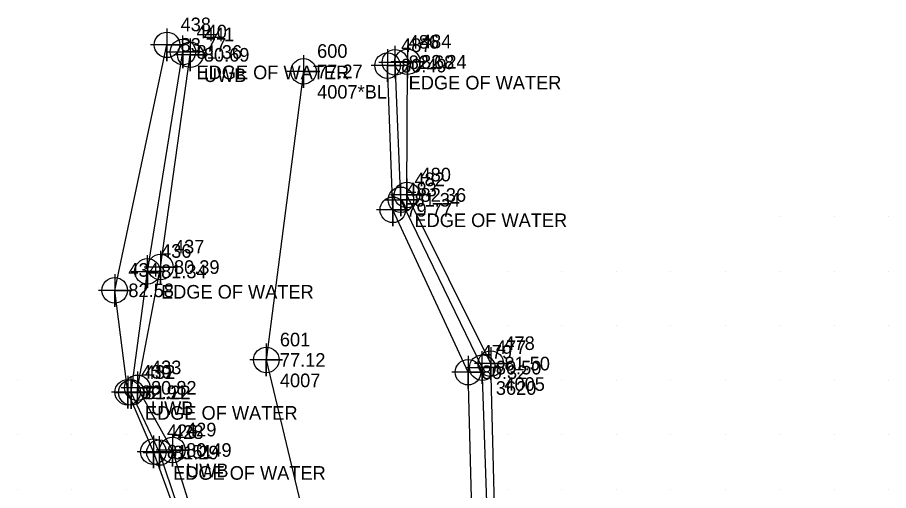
# Model space of a CAD drawing. Extents: x 1988140 to 1988766, y 249950 to 250250.
# Drawn here: x 1988380 to 1988540, y 250109.7 to 250196.6 of the extents above; entities that cross this region are included whole.
import ezdxf

# ---------------------------------------------------------------- set-up
doc = ezdxf.new("R2010")
doc.units = 0
for name, color, linetype in [('Exist DTM Breakline', 7, 'Continuous'), ('Exist DTM Breakline Cogo Comment', 7, 'Continuous'), ('Exist DTM Breakline Cogo Elevation', 7, 'Continuous'), ('Exist DTM Breakline Cogo Number', 7, 'Continuous'), ('Exist DTM Breakline Cogo Point CELL', 7, 'Continuous'), ('Exist DTM Breakline Underwater', 7, 'Continuous'), ('Exist DTM Breakline Underwater Cogo Comment', 7, 'Continuous'), ('Exist DTM Breakline Underwater Cogo Elevation', 7, 'Continuous'), ('Exist DTM Breakline Underwater Cogo Number', 7, 'Continuous'), ('Exist DTM Breakline Underwater Cogo Point CELL', 7, 'Continuous'), ('Exist DTM QL2 LIDAR Elevation Point', 7, 'Continuous'), ('Exist Hydro Stream or Body of Water', 7, 'Continuous'), ('Exist Hydro Stream or Body of Water Cogo Comment', 7, 'Continuous'), ('Exist Hydro Stream or Body of Water Cogo Elevation', 7, 'Continuous'), ('Exist Hydro Stream or Body of Water Cogo Number', 7, 'Continuous'), ('Exist Hydro Stream or Body of Water Cogo Point CELL', 7, 'Continuous')]:
    doc.layers.add(name, color=color, linetype=linetype)

msp = doc.modelspace()

# ---------------------------------------------------------------- linework, layer by layer
at = {"layer": 'Exist DTM Breakline'}
for points in [[(1988412.8446, 250078.35), (1988415.9225, 250086.8449), (1988404.9645, 250116.8632), (1988400.2626, 250127.7783), (1988397.8753, 250146.5011), (1988407.465, 250191.587)], [(1988466.937, 250133.0471), (1988451.5381, 250164.0148), (1988451.6259, 250188.4715)], [(1988502.0577, 249958.2531), (1988491.6502, 249990.2233), (1988485.1148, 250021.3111), (1988477.2086, 250042.1909), (1988478.2961, 250054.8431), (1988462.5221, 250084.1865), (1988467.6761, 250104.4545), (1988466.937, 250133.0471)]]:
    msp.add_lwpolyline(points, dxfattribs=at)
at = {"layer": 'Exist DTM Breakline Cogo Point CELL'}
for points in [[(1988407.465, 250194.587), (1988407.465, 250188.587), (1988407.465, 250191.587), (1988410.465, 250191.587), (1988404.465, 250191.587)], [(1988411.7424, 250192.7591), (1988411.7424, 250186.7591), (1988411.7424, 250189.7591), (1988414.7424, 250189.7591), (1988408.7424, 250189.7591)], [(1988447.9748, 250190.7776), (1988447.9748, 250184.7776), (1988447.9748, 250187.7776), (1988450.9748, 250187.7776), (1988444.9748, 250187.7776)], [(1988451.6259, 250191.4715), (1988451.6259, 250185.4715), (1988451.6259, 250188.4715), (1988454.6259, 250188.4715), (1988448.6259, 250188.4715)], [(1988451.5381, 250167.0148), (1988451.5381, 250161.0148), (1988451.5381, 250164.0148), (1988454.5381, 250164.0148), (1988448.5381, 250164.0148)], [(1988448.9433, 250164.2866), (1988448.9433, 250158.2866), (1988448.9433, 250161.2866), (1988451.9433, 250161.2866), (1988445.9433, 250161.2866)], [(1988406.2563, 250153.7734), (1988406.2563, 250147.7734), (1988406.2563, 250150.7734), (1988409.2563, 250150.7734), (1988403.2563, 250150.7734)], [(1988397.8753, 250149.5011), (1988397.8753, 250143.5011), (1988397.8753, 250146.5011), (1988400.8753, 250146.5011), (1988394.8753, 250146.5011)], [(1988466.937, 250136.0471), (1988466.937, 250130.0471), (1988466.937, 250133.0471), (1988469.937, 250133.0471), (1988463.937, 250133.0471)], [(1988462.7669, 250134.4643), (1988462.7669, 250128.4643), (1988462.7669, 250131.4643), (1988465.7669, 250131.4643), (1988459.7669, 250131.4643)], [(1988402.0332, 250131.5975), (1988402.0332, 250125.5975), (1988402.0332, 250128.5975), (1988405.0332, 250128.5975), (1988399.0332, 250128.5975)], [(1988400.2626, 250130.7783), (1988400.2626, 250124.7783), (1988400.2626, 250127.7783), (1988403.2626, 250127.7783), (1988397.2626, 250127.7783)], [(1988408.4707, 250120.1773), (1988408.4707, 250114.1773), (1988408.4707, 250117.1773), (1988411.4707, 250117.1773), (1988405.4707, 250117.1773)], [(1988404.9645, 250119.8632), (1988404.9645, 250113.8632), (1988404.9645, 250116.8632), (1988407.9645, 250116.8632), (1988401.9645, 250116.8632)]]:
    msp.add_lwpolyline(points, dxfattribs=at)
for centre in [(1988407.465, 250191.587), (1988411.7424, 250189.7591), (1988451.6259, 250188.4715), (1988447.9748, 250187.7776), (1988451.5381, 250164.0148), (1988448.9433, 250161.2866), (1988406.2563, 250150.7734), (1988397.8753, 250146.5011), (1988466.937, 250133.0471), (1988462.7669, 250131.4643), (1988400.2626, 250127.7783), (1988402.0332, 250128.5975), (1988404.9645, 250116.8632), (1988408.4707, 250117.1773)]:
    msp.add_circle(centre, 2.344, dxfattribs=at)
at = {"layer": 'Exist DTM Breakline Underwater'}
for points in [[(1988402.0332, 250128.5975), (1988406.2563, 250150.7734), (1988411.7424, 250189.7591)], [(1988472.6196, 250042.0736), (1988475.5478, 250051.8121), (1988460.2177, 250083.319), (1988463.5509, 250101.4082), (1988462.7669, 250131.4643), (1988448.9433, 250161.2866), (1988447.9748, 250187.7776)], [(1988432.5434, 250186.7094), (1988425.7037, 250133.7144), (1988438.98, 250078.1677), (1988446.627, 250047.162), (1988463.2661, 250001.9742), (1988462.1612, 249955.3502)], [(1988417.7936, 250087.3716), (1988408.4707, 250117.1773), (1988402.0332, 250128.5975)]]:
    msp.add_lwpolyline(points, dxfattribs=at)
at = {"layer": 'Exist DTM Breakline Underwater Cogo Point CELL'}
for points in [[(1988432.5434, 250189.7094), (1988432.5434, 250183.7094), (1988432.5434, 250186.7094), (1988435.5434, 250186.7094), (1988429.5434, 250186.7094)], [(1988425.7037, 250136.7144), (1988425.7037, 250130.7144), (1988425.7037, 250133.7144), (1988428.7037, 250133.7144), (1988422.7037, 250133.7144)]]:
    msp.add_lwpolyline(points, dxfattribs=at)
for centre in [(1988432.5434, 250186.7094), (1988425.7037, 250133.7144)]:
    msp.add_circle(centre, 2.344, dxfattribs=at)
at = {"layer": 'Exist DTM QL2 LIDAR Elevation Point'}
for p, q in [((1988520, 250160), (1988520, 250160)), ((1988530, 250160), (1988530, 250160)), ((1988540, 250160), (1988540, 250160)), ((1988470, 250150), (1988470, 250150)), ((1988480, 250150), (1988480, 250150)), ((1988490, 250150), (1988490, 250150)), ((1988500, 250150), (1988500, 250150)), ((1988510, 250150), (1988510, 250150)), ((1988520, 250150), (1988520, 250150)), ((1988530, 250150), (1988530, 250150)), ((1988540, 250150), (1988540, 250150)), ((1988470, 250140), (1988470, 250140)), ((1988480, 250140), (1988480, 250140)), ((1988490, 250140), (1988490, 250140)), ((1988500, 250140), (1988500, 250140)), ((1988510, 250140), (1988510, 250140)), ((1988520, 250140), (1988520, 250140)), ((1988530, 250140), (1988530, 250140)), ((1988540, 250140), (1988540, 250140)), ((1988380, 250130), (1988380, 250130)), ((1988390, 250130), (1988390, 250130)), ((1988470, 250130), (1988470, 250130)), ((1988480, 250130), (1988480, 250130)), ((1988490, 250130), (1988490, 250130)), ((1988500, 250130), (1988500, 250130)), ((1988510, 250130), (1988510, 250130)), ((1988520, 250130), (1988520, 250130)), ((1988530, 250130), (1988530, 250130)), ((1988540, 250130), (1988540, 250130)), ((1988380, 250120), (1988380, 250120)), ((1988390, 250120), (1988390, 250120)), ((1988400, 250120), (1988400, 250120)), ((1988470, 250120), (1988470, 250120)), ((1988480, 250120), (1988480, 250120)), ((1988490, 250120), (1988490, 250120)), ((1988500, 250120), (1988500, 250120)), ((1988510, 250120), (1988510, 250120)), ((1988520, 250120), (1988520, 250120)), ((1988530, 250120), (1988530, 250120)), ((1988540, 250120), (1988540, 250120)), ((1988380, 250110), (1988380, 250110)), ((1988390, 250110), (1988390, 250110)), ((1988400, 250110), (1988400, 250110)), ((1988470, 250110), (1988470, 250110)), ((1988480, 250110), (1988480, 250110)), ((1988490, 250110), (1988490, 250110)), ((1988500, 250110), (1988500, 250110)), ((1988510, 250110), (1988510, 250110)), ((1988520, 250110), (1988520, 250110)), ((1988530, 250110), (1988530, 250110)), ((1988540, 250110), (1988540, 250110))]:
    msp.add_line(p, q, dxfattribs=at)
at = {"layer": 'Exist Hydro Stream or Body of Water'}
for points in [[(1988426.3876, 249990.4525), (1988424.7619, 250020.0506), (1988425.9258, 250035.2006), (1988423.8559, 250042.0862), (1988414.1552, 250078.1093), (1988416.1489, 250087.1232), (1988406.0862, 250116.7149), (1988400.9098, 250127.7446), (1988403.8774, 250149.9815), (1988410.3915, 250190.2759)], [(1988474.7634, 250042.2609), (1988477.3409, 250054.8476), (1988462.0354, 250084.1709), (1988466.3899, 250102.3572), (1988465.3709, 250132.3106), (1988450.4249, 250163.1283), (1988449.3573, 250188.3896)]]:
    msp.add_lwpolyline(points, dxfattribs=at)
at = {"layer": 'Exist Hydro Stream or Body of Water Cogo Point CELL'}
for points in [[(1988407.3915, 250190.2759), (1988413.3915, 250190.2759), (1988410.3915, 250190.2759), (1988410.3915, 250187.2759), (1988410.3915, 250193.2759)], [(1988446.3573, 250188.3896), (1988452.3573, 250188.3896), (1988449.3573, 250188.3896), (1988449.3573, 250185.3896), (1988449.3573, 250191.3896)], [(1988447.4249, 250163.1283), (1988453.4249, 250163.1283), (1988450.4249, 250163.1283), (1988450.4249, 250160.1283), (1988450.4249, 250166.1283)], [(1988400.8774, 250149.9815), (1988406.8774, 250149.9815), (1988403.8774, 250149.9815), (1988403.8774, 250146.9815), (1988403.8774, 250152.9815)], [(1988462.3709, 250132.3106), (1988468.3709, 250132.3106), (1988465.3709, 250132.3106), (1988465.3709, 250129.3106), (1988465.3709, 250135.3106)], [(1988397.9098, 250127.7446), (1988403.9098, 250127.7446), (1988400.9098, 250127.7446), (1988400.9098, 250124.7446), (1988400.9098, 250130.7446)], [(1988403.0862, 250116.7149), (1988409.0862, 250116.7149), (1988406.0862, 250116.7149), (1988406.0862, 250113.7149), (1988406.0862, 250119.7149)]]:
    msp.add_lwpolyline(points, dxfattribs=at)
for centre in [(1988410.3915, 250190.2759), (1988449.3573, 250188.3896), (1988450.4249, 250163.1283), (1988403.8774, 250149.9815), (1988465.3709, 250132.3106), (1988400.9098, 250127.7446), (1988406.0862, 250116.7149)]:
    msp.add_circle(centre, 2.344, dxfattribs=at)

# ---------------------------------------------------------------- texts
at = {"layer": 'Exist DTM Breakline Cogo Comment'}
for s, p in [('UWB', (1988414.2424, 250184.7591)), ('4005', (1988469.437, 250128.0471)), ('UWB', (1988404.5332, 250123.5975)), ('UWB', (1988410.9707, 250112.1773))]:
    msp.add_text(s, height=2.5, dxfattribs=at).set_placement(p)
at = {"layer": 'Exist DTM Breakline Cogo Elevation'}
for s, p in [('83.77', (1988409.965, 250190.337)), ('80.69', (1988414.2424, 250188.5091)), ('80.49', (1988450.4748, 250186.5276)), ('82.24', (1988454.1259, 250187.2215)), ('82.36', (1988454.0381, 250162.7648)), ('79.77', (1988451.4433, 250160.0366)), ('80.39', (1988408.7563, 250149.5234)), ('82.58', (1988400.3753, 250145.2511)), ('81.50', (1988469.437, 250131.7971)), ('80.32', (1988465.2669, 250130.2143)), ('80.82', (1988404.5332, 250127.3475)), ('82.91', (1988402.7626, 250126.5283)), ('80.49', (1988410.9707, 250115.9273)), ('81.51', (1988407.4645, 250115.6132))]:
    msp.add_text(s, height=2.5, dxfattribs=at).set_placement(p)
at = {"layer": 'Exist DTM Breakline Cogo Number'}
for s, p in [('438', (1988409.965, 250194.087)), ('441', (1988414.2424, 250192.2591)), ('487', (1988450.4748, 250190.2776)), ('484', (1988454.1259, 250190.9715)), ('480', (1988454.0381, 250166.5148)), ('483', (1988451.4433, 250163.7866)), ('437', (1988408.7563, 250153.2734)), ('434', (1988400.3753, 250149.0011)), ('478', (1988469.437, 250135.5471)), ('479', (1988465.2669, 250133.9643)), ('430', (1988402.7626, 250130.2783)), ('433', (1988404.5332, 250131.0975)), ('426', (1988407.4645, 250119.3632)), ('429', (1988410.9707, 250119.6773))]:
    msp.add_text(s, height=2.5, dxfattribs=at).set_placement(p)
at = {"layer": 'Exist DTM Breakline Underwater Cogo Comment'}
for s, p in [('4007*BL', (1988435.0434, 250181.7094)), ('4007', (1988428.2037, 250128.7144))]:
    msp.add_text(s, height=2.5, dxfattribs=at).set_placement(p)
at = {"layer": 'Exist DTM Breakline Underwater Cogo Elevation'}
for s, p in [('77.27', (1988435.0434, 250185.4594)), ('77.12', (1988428.2037, 250132.4644))]:
    msp.add_text(s, height=2.5, dxfattribs=at).set_placement(p)
at = {"layer": 'Exist DTM Breakline Underwater Cogo Number'}
for s, p in [('600', (1988435.0434, 250189.2094)), ('601', (1988428.2037, 250136.2144))]:
    msp.add_text(s, height=2.5, dxfattribs=at).set_placement(p)
at = {"layer": 'Exist Hydro Stream or Body of Water Cogo Comment'}
for s, p in [('EDGE OF WATER', (1988412.8915, 250185.2759)), ('EDGE OF WATER', (1988451.8573, 250183.3896)), ('EDGE OF WATER', (1988452.9249, 250158.1283)), ('EDGE OF WATER', (1988406.3774, 250144.9815)), ('3620', (1988467.8709, 250127.3106)), ('EDGE OF WATER', (1988403.4098, 250122.7446)), ('EDGE OF WATER', (1988408.5862, 250111.7149))]:
    msp.add_text(s, height=2.5, dxfattribs=at).set_placement(p)
at = {"layer": 'Exist Hydro Stream or Body of Water Cogo Elevation'}
for s, p in [('81.36', (1988412.8915, 250189.0259)), ('82.68', (1988451.8573, 250187.1396)), ('81.34', (1988452.9249, 250161.8783)), ('81.34', (1988406.3774, 250148.7315)), ('80.50', (1988467.8709, 250131.0606)), ('81.22', (1988403.4098, 250126.4946)), ('81.29', (1988408.5862, 250115.4649))]:
    msp.add_text(s, height=2.5, dxfattribs=at).set_placement(p)
at = {"layer": 'Exist Hydro Stream or Body of Water Cogo Number'}
for s, p in [('440', (1988412.8915, 250192.7759)), ('486', (1988451.8573, 250190.8896)), ('482', (1988452.9249, 250165.6283)), ('436', (1988406.3774, 250152.4815)), ('477', (1988467.8709, 250134.8106)), ('432', (1988403.4098, 250130.2446)), ('428', (1988408.5862, 250119.2149))]:
    msp.add_text(s, height=2.5, dxfattribs=at).set_placement(p)

doc.saveas('drawing.dxf')
